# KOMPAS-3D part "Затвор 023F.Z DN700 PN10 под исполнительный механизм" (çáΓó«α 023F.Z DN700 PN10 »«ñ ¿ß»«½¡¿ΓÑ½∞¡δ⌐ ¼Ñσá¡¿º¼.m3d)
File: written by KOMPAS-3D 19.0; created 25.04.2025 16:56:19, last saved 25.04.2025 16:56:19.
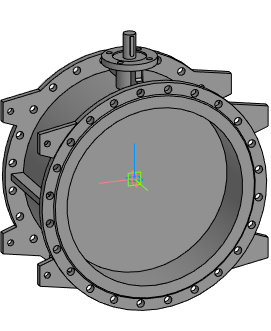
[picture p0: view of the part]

Document properties: Автор: Евгений; Полное имя файла: E:\Dendor Работа Сачек\3D для проекитирвщиков\1.7 Тип 023F.Z Затвор дисковый поворотный фланцевый с двумя эксцентриками\stp_Тип 023F.Z. Затвор под исполн. механизм\Затвор 023F.Z DN700 PN10 под исполнительный механизм.m3d

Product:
- Part/product: Затвор 023F.Z DN700 PN10 под исполнительный механизм

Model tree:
1. Операция без истории:1  (labels: Затвор 023F.Z DN700 PN10 под исполнительный механизм)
